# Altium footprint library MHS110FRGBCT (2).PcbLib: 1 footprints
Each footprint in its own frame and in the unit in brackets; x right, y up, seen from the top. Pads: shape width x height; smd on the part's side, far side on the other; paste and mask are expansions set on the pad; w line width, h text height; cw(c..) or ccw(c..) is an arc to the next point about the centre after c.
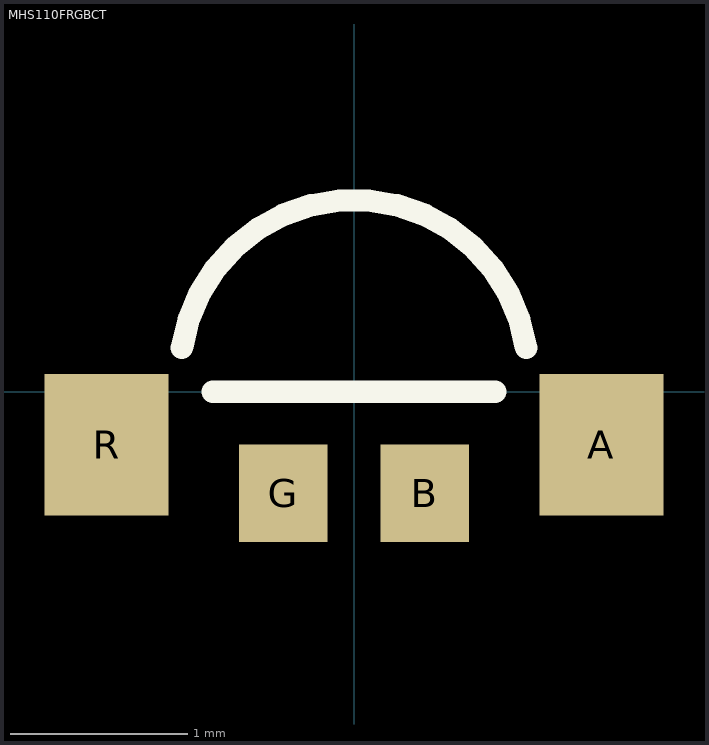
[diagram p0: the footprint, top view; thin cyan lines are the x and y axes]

## MHS110FRGBCT [mm]
pads (4):
  rect 0.7x0.8 smd: A(1.4,-0.3) R(-1.4,-0.3)
  rect 0.5x0.55 smd: B(0.4,-0.575) G(-0.4,-0.575)
Top Overlay:
  lines w0.127: -0.973,0.25 cw(c0,0.1) 0.973,0.25 ; -0.8,0 0.8,0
